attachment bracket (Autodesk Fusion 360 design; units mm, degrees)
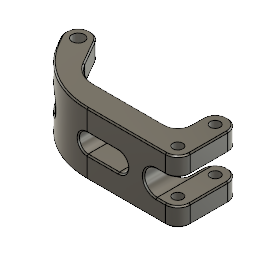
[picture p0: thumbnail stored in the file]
sketch "Sketch1" plane through (0, 0, 0) normal (0, 1, 0) x axis (1, 0, 0)
  line L1 (42.8408, 20) -> (-14.6314, 20)
  line L2 (52.8408, 50) -> (52.8408, 30)
  line L3 (72.8408, 50) -> (52.8408, 50)
  line L4 (72.8408, 0) -> (72.8408, 50)
  line L5 (0, 0) -> (72.8408, 0)
  line L6 (62.8408, 40) -> (62.8408, 50)
  line L7 (62.8408, 10) -> (62.8408, 40)
  line L8 (62.8408, 0) -> (62.8408, 10)
  line L9 (-43.4989, 50) -> (-31.9519, 30)
  line L10 (-56.5882, 32.6712) -> (-60.8194, 40)
  arc A1 centre (-52.1592, 45) radius 10 clockwise from (-60.8194, 40) to (-43.4989, 50)
  arc A2 centre (42.8408, 30) radius 10 clockwise from (52.8408, 30) to (42.8408, 20)
  circle C1 centre (-52.1592, 45) radius 5
  circle C2 centre (62.8408, 10) radius 4
  circle C3 centre (62.8408, 40) radius 4
  arc A3 centre (-14.6314, 40) radius 20 clockwise from (-14.6314, 20) to (-31.9519, 30)
  arc A4 centre (0, 65.3424) radius 65.3424 clockwise from (0, 0) to (-56.5882, 32.6712)
  point P1 (0, 0)
  point P12 (0, 0)
  point P14 (62.8408, 50)
  point P17 (62.8408, 0)
  point P16 (62.8408, 10)
  point P18 (62.8408, 10)
  point P15 (62.8408, 40)
  point P19 (62.8408, 40)
  point P23 (0, 0)
  point P11 (72.8408, 0)
  point P13 (-52.1592, 45)
  point P9 (52.8408, 50)
  point P10 (72.8408, 50)
  tangent L1 A2
  perpendicular L1 L2
  perpendicular L2 L3
  perpendicular L3 L4
  coincident P1 P12
  concentric A1 C1
  horizontal L5
  tangent A2 L2
  midpoint L3 P14
  perpendicular L3 L6
  perpendicular L3 L7
  coincident L5 P17
  perpendicular L5 L8
  equal L6 L8
  coincident P16 P18
  coincident P15 P19
  equal C2 C3
  tangent L1 A3
  parallel L9 L10
  tangent L10 A4
  tangent A1 L10
  tangent A1 L9
  tangent A3 L9
  coincident P1 P23
  tangent L5 A4
  dimension "d1" distance P11 P13 = 125
  dimension "d2" distance P9 P10 = 20
  dimension "d3" distance P10 P11 = 50
  dimension "d4" radius A2 = 10
  dimension "d6" radius A1 = 10
  dimension "d8" diameter C1 = 10
  dimension "d9" distance L1 L5 = 20
  dimension "d12" distance P16 P17 = 10
  dimension "d13" diameter C3 = 8
  dimension "d14" distance P13 P18 = 35
  dimension "d15" angle L5 L9 = 120
  dimension "d16" radius A3 = 20
extrude "Extrude1" new body sketch "Sketch1" profile of A1 L1 A2 L2 L3 L4 L5 C1 C2 C3 A3 L9 L10 A4 distance 25
sketch "Sketch2" plane through (0, 0, 0) normal (0, 1, 0) x axis (1, 0, 0)
  circle C1 centre (-52.1592, 45) radius 5
  circle C2 centre (-52.1592, 45) radius 37.5
  concentric C1 C2
  dimension "d19" diameter C2 = 75
extrude "Extrude2" cut sketch "Sketch2" distance 10
fillet "Fillet1" radius 10
fillet "Fillet2" radius 10
sketch "Sketch3" plane through (0, 0, -20) normal (0, 0, -1) x axis (-1, 0, 0)
  line L1 (14.6314, 25) -> (14.6314, -25)
  line L2 (-42.8408, 25) -> (14.6314, 25)
  line L3 (-42.8408, -25) -> (-42.8408, 25)
  line L4 (14.6314, -25) -> (-42.8408, -25)
  line L5 (-25, 7.5) -> (0, 7.5)
  line L6 (0, -7.5) -> (-25, -7.5)
  line L7 (-25, 0) -> (0, 0)
  line L8 (0, 25) -> (0, -25)
  arc A1 centre (-25, 0) radius 7.5 clockwise from (-25, -7.5) to (-25, 7.5)
  arc A2 centre (0, 0) radius 7.5 clockwise from (0, 7.5) to (0, -7.5)
  point P1 (0, 0)
  point P10 (0, 0)
  point P11 (-25, 0)
  tangent L5 A1
  tangent A1 L6
  parallel L5 L6
  tangent L6 A2
  tangent L5 A2
  perpendicular L7 L8
  coincident P1 P10
  dimension "d24" diameter A1 = 15
  dimension "d25" distance P10 P11 = 25
extrude "Extrude3" cut sketch "Sketch3" profile of L5 A1 L6 A2 L8 no distance stored
fillet "Fillet3" radius 10
sketch "Sketch4" plane through (0, 0, 0) normal (0, 1, 0) x axis (1, 0, 0)
  line L1 (45.3408, 10) -> (45.3408, 40)
  line L2 (80.3408, 40) -> (80.3408, 10)
  line L3 (62.8408, 10) -> (62.8408, 40)
  line L4 (45.3408, -7.5) -> (45.3408, 10)
  line L5 (80.3408, -7.5) -> (45.3408, -7.5)
  line L6 (80.3408, 10) -> (80.3408, -7.5)
  circle C1 centre (62.8408, 40) radius 4
  circle C2 centre (62.8408, 10) radius 4
  arc A1 centre (62.8408, 10) radius 17.5 clockwise from (80.3408, 10) to (45.3408, 10)
  arc A2 centre (62.8408, 40) radius 17.5 clockwise from (45.3408, 40) to (80.3408, 40)
  point P3 (62.8408, 10)
  point P9 (62.8408, 10)
  point P2 (62.8408, 40)
  point P8 (62.8408, 40)
  tangent L1 A1
  tangent A1 L2
  parallel L1 L2
  tangent L2 A2
  tangent L1 A2
  coincident P3 P9
  vertical L3
  coincident P2 P8
  tangent A1 L4
  perpendicular L2 L5
  tangent A1 L6
  tangent A1 L5
  dimension "d28" diameter A1 = 35
extrude "Extrude4" cut sketch "Sketch4" profile of C1 C2 L1 A1 L2 A2 distance 10
fillet "Fillet4" radius 10
chamfer "Chamfer1" distance 1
